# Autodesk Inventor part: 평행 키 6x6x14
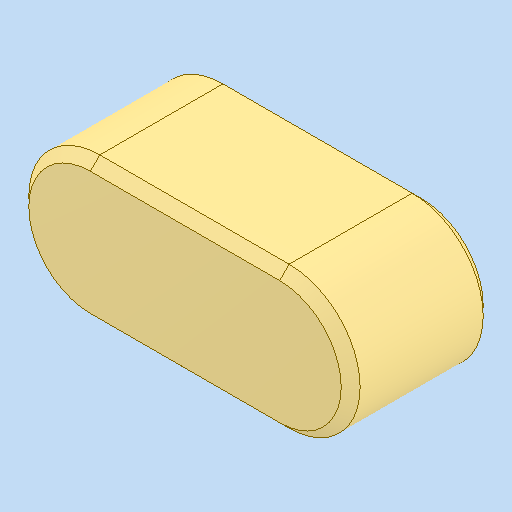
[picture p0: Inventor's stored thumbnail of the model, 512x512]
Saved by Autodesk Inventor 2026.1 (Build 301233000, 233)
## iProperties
Created: 2025-09
Part Number: 평행 키 6x6x14
Material: 강철, 연강
Description: 키 및 해당 키홈
Document SubType Name: Modeling
Designer: PC-30
Density: 7.85 g/cm^3
Appearance: 기본값
Author: jhkim
Sending System: Autodesk Inventor 2026
Preprocessor: ST-DEVELOPER v20.1
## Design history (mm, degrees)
feature "Solid1"
node "솔리드1"
